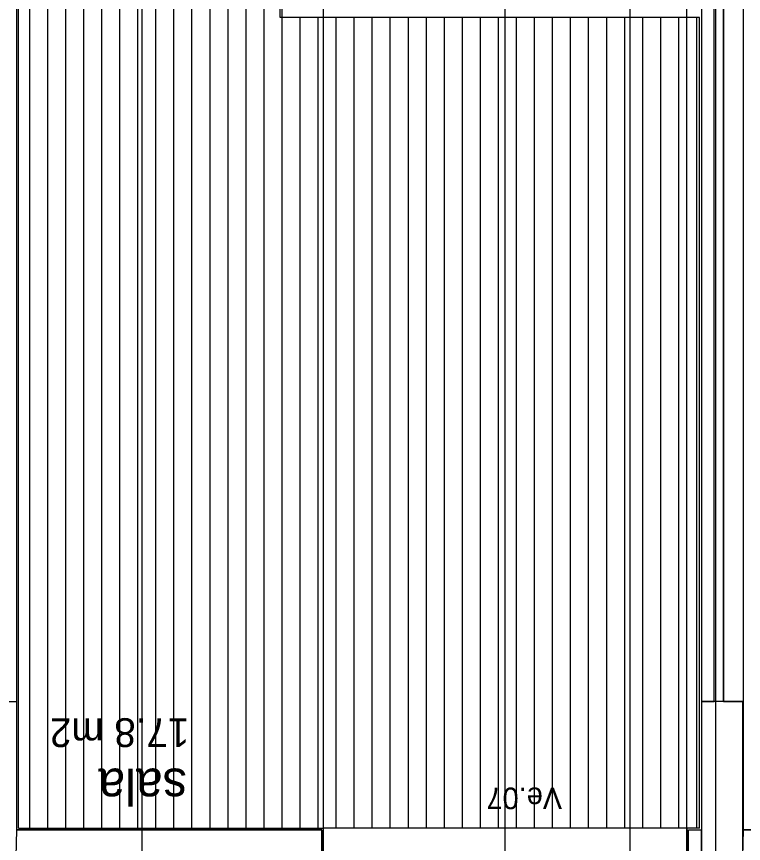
# Model space of a CAD drawing. Extents: x 1278 to 1356, y -253.7 to -224.
# Drawn here: x 1303.561 to 1307.592, y -243.659 to -239.071 of the extents above; entities that cross this region are included whole.
import ezdxf

# ---------------------------------------------------------------- set-up
doc = ezdxf.new("R2010")
doc.units = 0
for name, color, linetype in [('Level 1', 7, 'Continuous'), ('Level 10', 7, 'Continuous'), ('Level 2', 7, 'Continuous'), ('Level 40', 7, 'Continuous'), ('Level 59', 7, 'Continuous'), ('Level 60', 7, 'Continuous'), ('Level 65', 7, 'Continuous'), ('Level 66', 7, 'Continuous'), ('Level 67', 7, 'Continuous'), ('Level 70', 7, 'Continuous'), ('Level 93', 7, 'Continuous')]:
    doc.layers.add(name, color=color, linetype=linetype)

msp = doc.modelspace()

# ---------------------------------------------------------------- linework, layer by layer
at = {"layer": 'Level 1'}
for p, q in [((1305.254, -243.584), (1303.5623, -243.584)), ((1305.254, -243.914), (1305.254, -243.584)), ((1309.284, -243.584), (1307.5923, -243.584))]:
    msp.add_line(p, q, dxfattribs=at)
at = {"layer": 'Level 10'}
for p, q in [((1303.6337, -243.574), (1303.6337, -235.1552)), ((1303.7337, -243.574), (1303.7337, -235.1552)), ((1303.8337, -243.574), (1303.8337, -235.1552)), ((1303.9337, -243.574), (1303.9337, -235.1552)), ((1304.0337, -243.574), (1304.0337, -235.1552)), ((1304.1337, -243.574), (1304.1337, -235.1552)), ((1304.2337, -243.574), (1304.2337, -235.1552)), ((1304.3337, -243.574), (1304.3337, -235.1552)), ((1304.4337, -243.574), (1304.4337, -235.1552)), ((1304.5337, -243.574), (1304.5337, -235.1552)), ((1304.6337, -243.574), (1304.6337, -235.1552)), ((1304.7337, -243.574), (1304.7337, -235.1552)), ((1304.8337, -243.574), (1304.8337, -235.1552)), ((1304.9337, -243.574), (1304.9337, -235.1552)), ((1305.0337, -243.574), (1305.0337, -238.974)), ((1305.1337, -243.574), (1305.1337, -239.0763)), ((1305.2337, -243.574), (1305.2337, -239.0763)), ((1305.3337, -243.574), (1305.3337, -239.0763)), ((1305.4337, -243.574), (1305.4337, -239.0763)), ((1305.5337, -243.574), (1305.5337, -239.0763)), ((1305.6337, -243.574), (1305.6337, -239.0763)), ((1305.7337, -243.574), (1305.7337, -239.0763)), ((1305.8337, -243.574), (1305.8337, -239.0763)), ((1305.9337, -243.574), (1305.9337, -239.0763)), ((1306.0337, -243.574), (1306.0337, -239.0763)), ((1306.1337, -243.574), (1306.1337, -239.0763)), ((1306.2337, -243.574), (1306.2337, -239.0763)), ((1306.3337, -243.574), (1306.3337, -239.0763)), ((1306.4337, -243.574), (1306.4337, -239.0763)), ((1306.5337, -243.574), (1306.5337, -239.0763)), ((1306.6337, -243.574), (1306.6337, -239.0763)), ((1306.7337, -243.574), (1306.7337, -239.0763)), ((1306.8337, -243.574), (1306.8337, -239.0763)), ((1306.9337, -243.574), (1306.9337, -239.0763)), ((1307.0337, -243.574), (1307.0337, -239.0763)), ((1307.1337, -243.574), (1307.1337, -239.0763)), ((1307.2337, -243.574), (1307.2337, -239.0763)), ((1307.3337, -243.574), (1307.3337, -239.0763))]:
    msp.add_line(p, q, dxfattribs=at)
at = {"layer": 'Level 2'}
msp.add_line((1307.279, -243.574), (1305.264, -243.574), dxfattribs=at)
at = {"layer": 'Level 59'}
msp.add_lwpolyline([(1312.108, -245.3846), (1306.9649, -245.3846), (1306.9649, -231.5072), (1312.108, -231.5072)], close=True, dxfattribs=at)
at = {"layer": 'Level 65'}
for p, q in [((1303.5723, -243.574), (1303.5723, -235.1552)), ((1305.0223, -239.0763), (1305.0223, -237.9048)), ((1307.349, -239.0763), (1305.0223, -239.0763)), ((1307.349, -243.574), (1307.349, -239.0763)), ((1303.5723, -243.574), (1305.264, -243.574)), ((1305.264, -243.924), (1305.264, -243.574)), ((1307.279, -243.574), (1307.279, -243.924)), ((1307.349, -243.574), (1307.279, -243.574))]:
    msp.add_line(p, q, dxfattribs=at)
at = {"layer": 'Level 66'}
for p, q in [((1303.5623, -243.584), (1303.5623, -232.264)), ((1303.5623, -243.584), (1303.5623, -232.264)), ((1303.5623, -243.584), (1303.5623, -232.264)), ((1307.5919, -243.584), (1307.5919, -232.264)), ((1307.5919, -243.584), (1307.5919, -232.264)), ((1307.5919, -243.584), (1307.5919, -232.264)), ((1307.4294, -242.8713), (1307.4294, -236.9213)), ((1307.4823, -242.8713), (1307.4823, -236.9213)), ((1307.359, -239.0663), (1307.3594, -242.8713)), ((1307.2884, -243.914), (1307.2884, -243.584)), ((1307.2884, -243.584), (1307.359, -243.584)), ((1307.359, -243.804), (1307.359, -243.584))]:
    msp.add_line(p, q, dxfattribs=at)
msp.add_lwpolyline([(1307.359, -243.7713), (1307.589, -243.7713), (1307.589, -242.8713), (1307.359, -242.8713)], close=True, dxfattribs=at)
msp.add_lwpolyline([(1307.359, -243.7713), (1307.589, -243.7713), (1307.589, -242.8713), (1307.359, -242.8713)], close=True, dxfattribs=at)
at = {"layer": 'Level 67'}
for points in [[(1303.4527, -242.8713), (1303.5627, -242.8713), (1303.5627, -236.9213), (1303.4527, -236.9213)], [(1307.3594, -242.8713), (1307.4294, -242.8713), (1307.4294, -236.9213), (1307.3594, -236.9213)], [(1307.4823, -242.8713), (1307.5923, -242.8713), (1307.5923, -236.9213), (1307.4823, -236.9213)], [(1303.5623, -243.584), (1305.254, -243.584), (1305.254, -243.914), (1303.2584, -243.914), (1303.2584, -243.584), (1303.329, -243.584), (1303.329, -243.804), (1305.184, -243.804), (1305.184, -243.734), (1303.5594, -243.734)], [(1307.5923, -243.584), (1309.284, -243.584), (1309.284, -243.914), (1307.2884, -243.914), (1307.2884, -243.584), (1307.359, -243.584), (1307.359, -243.804), (1309.214, -243.804), (1309.214, -243.734), (1307.5894, -243.734)]]:
    msp.add_lwpolyline(points, close=True, dxfattribs=at)
at = {"layer": 'Level 70'}
msp.add_line((1307.439, -250.7923), (1307.439, -229.6198), dxfattribs=at)
at = {"layer": 'Level 93'}
for p, q in [((1304.2565, -246.757), (1304.2565, -236.1407)), ((1305.264, -246.757), (1305.264, -236.1407)), ((1306.2715, -246.757), (1306.2715, -236.1407)), ((1307.279, -246.757), (1307.279, -236.1407))]:
    msp.add_line(p, q, dxfattribs=at)

# ---------------------------------------------------------------- texts
at = {"layer": 'Level 40'}
msp.add_text('Ve.07', height=0.12, rotation=180, dxfattribs=at).set_placement((1306.5864, -243.3487))
at = {"layer": 'Level 60'}
for s, height, p in [('17.8 m2', 0.16, (1304.519, -242.9642)), ('sala', 0.2, (1304.5048, -243.2438))]:
    msp.add_text(s, height=height, rotation=180, dxfattribs=at).set_placement(p)

doc.saveas('drawing.dxf')
